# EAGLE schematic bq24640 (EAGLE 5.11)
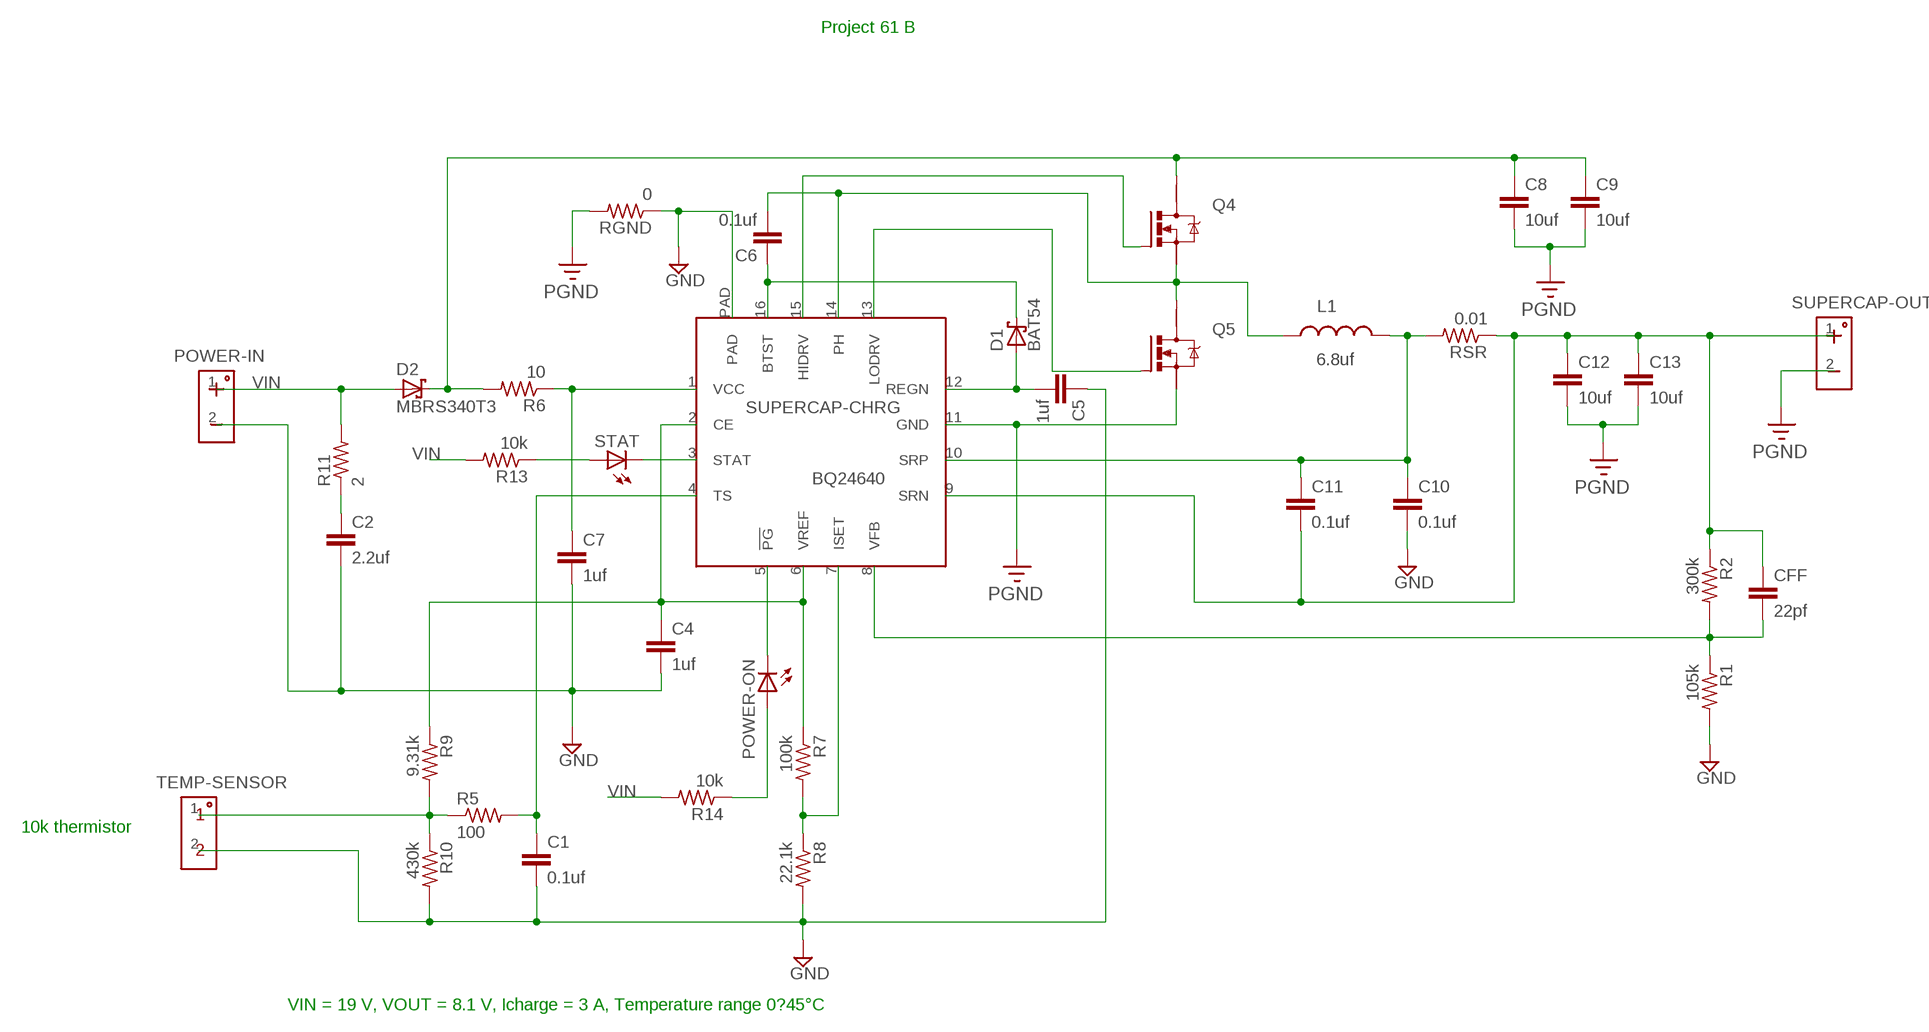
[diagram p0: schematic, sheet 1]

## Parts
C1  0.1uf  C-EUC0805  [C0805]
C2  2.2uf  C-EUC0805  [C0805]
C4  1uf  C-EUC0805  [C0805]
C5  1uf  C-EUC0805  [C0805]
C6  0.1uf  C-EUC0805  [C0805]
C7  1uf  C-EUC0805  [C0805]
C8  10uf  C-EUC0805  [C0805]
C9  10uf  C-EUC0805  [C0805]
C10  0.1uf  C-EUC0805  [C0805]
C11  0.1uf  C-EUC0805  [C0805]
C12  10uf  C-EUC0805  [C0805]
C13  10uf  C-EUC0805  [C0805]
CFF  22pf  C-EUC0805  [C0805]
D1  BAT54  [SOT23]
D2  MBRS340T3  [SMC]
L1  6.8uf  INDUCTOR1210  [1210]
POWER-IN  HEADER-POWERSMD  [HEADER-POWER-SMD]
POWER-ON  LEDCHIPLED_0805  [CHIPLED_0805]
Q4  N-MOSFET-SO8S  [SO-08]
Q5  N-MOSFET-SO8S  [SO-08]
R1  105k  R-US_R0805  [R0805]
R2  300k  R-US_R0805  [R0805]
R5  100  R-US_R0805  [R0805]
R6  10  R-US_R0805  [R0805]
R7  100k  R-US_R0805  [R0805]
R8  22.1k  R-US_R0805  [R0805]
R9  9.31k  R-US_R0805  [R0805]
R10  430k  R-US_R0805  [R0805]
R11  2  R-US_R0805  [R0805]
R13  10k  R-US_R0805  [R0805]
R14  10k  R-US_R0805  [R0805]
RGND  0  R-US_R0805  [R0805]
RSR  0.01  R-US_R1206  [R1206]
STAT  LEDCHIPLED_0805  [CHIPLED_0805]
SUPERCAP-CHRG  BQ24640  [QFN16-3.5X3.5-0.5PITCH]
SUPERCAP-OUT  HEADER-POWERSMD  [HEADER-POWER-SMD]
TEMP-SENSOR  HEADER-2SMD  [HEADER-POWER-SMD]

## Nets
GND: C1.2 C2.2 C4.2 C5.1 C7.2 C10.2 POWER-IN.2 R1.2 R8.2 R10.2 RGND.1 SUPERCAP-CHRG.PAD TEMP-SENSOR.2
N$1: C7.1 R6.1 SUPERCAP-CHRG.1(VCC)
N$2: C8.1 C9.1 D2.C Q4.5(D) R6.2
N$3: C10.1 C11.1 L1.2 RSR.2 SUPERCAP-CHRG.10(SRP)
N$5: C2.1 R11.1
N$6: C5.2 D1.1(A) SUPERCAP-CHRG.12(REGN)
N$7: C6.1 D1.3(C) SUPERCAP-CHRG.16(BTST)
N$8: C6.2 L1.1 Q4.1(S) Q5.5(D) SUPERCAP-CHRG.14(PH)
N$9: C11.2 C12.1 C13.1 CFF.1 R2.1 RSR.1 SUPERCAP-CHRG.9(SRN) SUPERCAP-OUT.1
N$10: Q4.4(G) SUPERCAP-CHRG.15(HIDRV)
N$11: Q5.4(G) SUPERCAP-CHRG.13(LODRV)
N$13: STAT.C SUPERCAP-CHRG.3(STAT)
N$14: CFF.2 R1.1 R2.2 SUPERCAP-CHRG.8(VFB)
N$15: R7.2 R8.1 SUPERCAP-CHRG.7(ISET)
N$16: C4.1 R7.1 R9.1 SUPERCAP-CHRG.2(CE) SUPERCAP-CHRG.6(VREF)
N$18: R13.1 STAT.A
N$19: POWER-ON.A R14.1
N$20: POWER-ON.C SUPERCAP-CHRG.5(!PG)
N$21: R5.1 R9.2 R10.1 TEMP-SENSOR.1
N$22: C1.1 R5.2 SUPERCAP-CHRG.4(TS)
PGND: C8.2 C9.2 C12.2 C13.2 Q5.1(S) RGND.2 SUPERCAP-CHRG.11(GND) SUPERCAP-OUT.2
VIN: D2.A POWER-IN.1 R11.2 R13.2 R14.2
Unconnected: Q4.2(S) Q4.3(S) Q4.6(D) Q4.7(D) Q4.8(D) Q5.2(S) Q5.3(S) Q5.6(D) Q5.7(D) Q5.8(D)

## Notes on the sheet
- Project 61 B
- 10k thermistor
- VIN = 19 V, VOUT = 8.1 V, Icharge = 3 A, Temperature range 0?45°C

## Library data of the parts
C1 C2 C4-C13 CFF = rcl:C-EU: CAPACITOR, European symbol
D1 = diode:BAT54: Schottky Diodes
D2 = diode:MBRS3*0T3: SCHOTTKY BARRIER RECTIFIER 3.0 AMPERES 20, 30, 40 VOLT
L1 = SparkFun2011-02-20:INDUCTOR: Inductors
POWER-IN SUPERCAP-OUT = trl:HEADER-POWER
POWER-ON STAT = led:LED: LED
Q4 Q5 = transistor-power:N-MOSFET-SO8: N-Channel MOSFET Example: FDS7760A; N-Channel Logic Level PowerTrench® MOSFET FDS2572; N-Channel UltraFET® Trench MOSFET Source: www.fairchildsemi.com
R1 R2 R5-R11 R13 R14 RGND RSR = resistor:R-US_: RESISTOR, American symbol
SUPERCAP-CHRG = trl:BQ24640
TEMP-SENSOR = trl:HEADER-2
